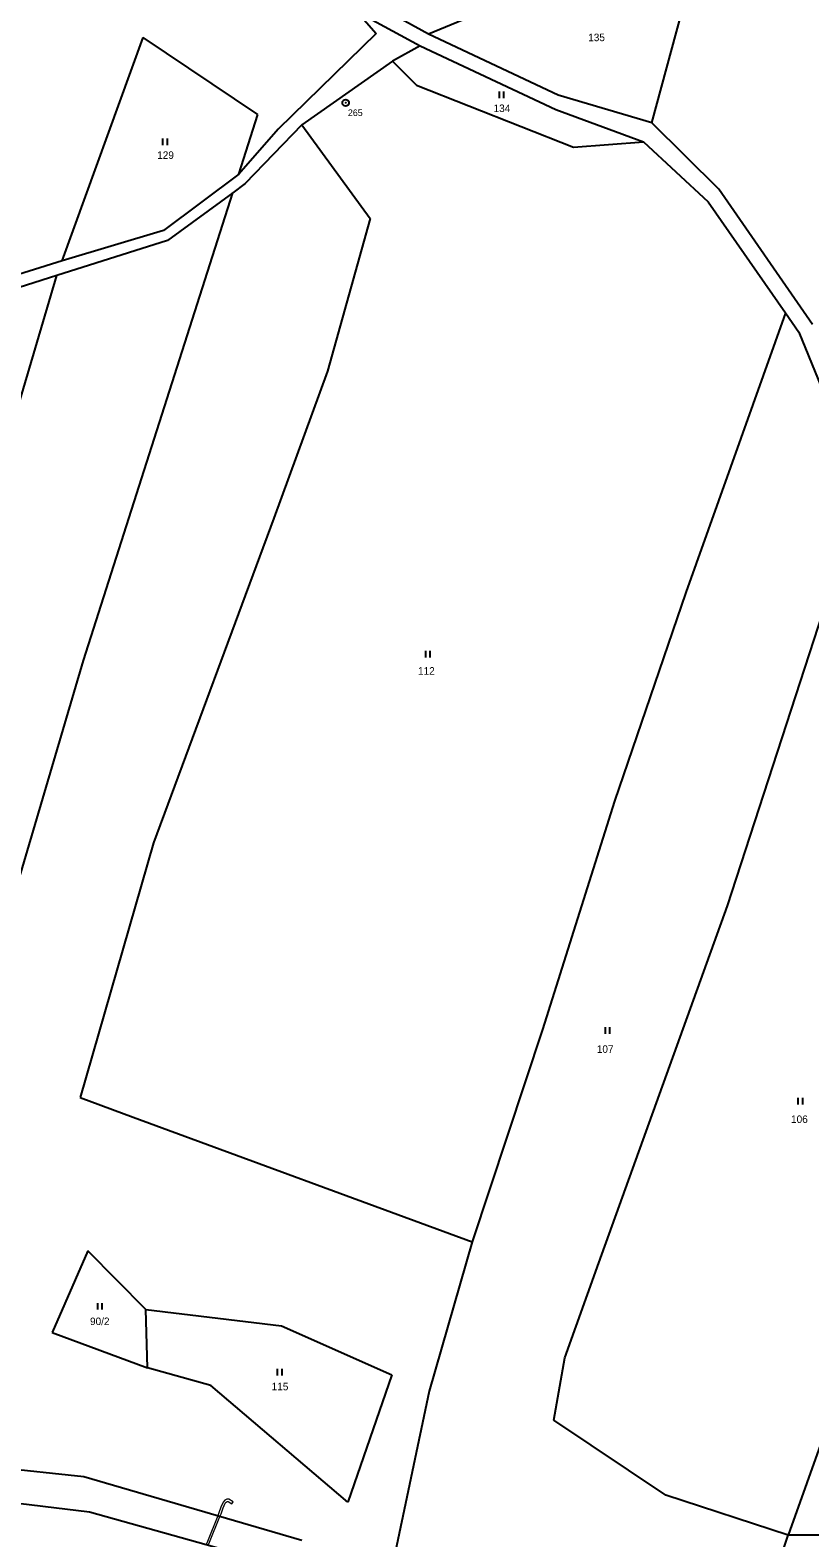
# Model space of a CAD drawing. Extents: x -791548 to -789311, y -1142631 to -1140855.
# Drawn here: x -790140.3 to -789963.7, y -1142168.7 to -1141827.2 of the extents above; entities that cross this region are included whole.
import ezdxf
from ezdxf.enums import TextEntityAlignment as Align

# ---------------------------------------------------------------- set-up
doc = ezdxf.new("R2010")
doc.units = 0
doc.header["$LTSCALE"] = 0.68
for name, color, linetype, lineweight in [('1', 7, 'Continuous', 25), ('13', 7, 'Continuous', 13), ('3', 7, 'Continuous', 25), ('8', 7, 'Continuous', 25)]:
    doc.layers.add(name, color=color, linetype=linetype, lineweight=lineweight)
doc.layers.add('2', color=7, linetype='Continuous')

msp = doc.modelspace()

# ---------------------------------------------------------------- linework, layer by layer
at = {"layer": '1'}
for p, q in [((-789999.52, -1141848.2), (-789985.77, -1141797.39)), ((-790001.61, -1141808.07), (-790050.12, -1141828.08)), ((-790050.12, -1141828.08), (-790064.67, -1141820.05)), ((-790066.32, -1141822.97), (-790051.96, -1141830.74)), ((-790066.32, -1141822.97), (-790061.95, -1141827.96)), ((-790133.08, -1141879.48), (-790114.77, -1141828.85)), ((-790088.74, -1141846.3), (-790114.77, -1141828.85)), ((-790061.95, -1141827.96), (-790084.19, -1141849.65)), ((-790020.74, -1141841.92), (-790050.12, -1141828.08)), ((-790051.96, -1141830.74), (-790058.23, -1141834.22)), ((-790051.96, -1141830.74), (-790021.22, -1141845.13)), ((-790058.23, -1141834.22), (-790078.78, -1141848.66)), ((-790058.23, -1141834.22), (-790052.8, -1141839.64)), ((-790052.8, -1141839.64), (-790017.22, -1141853.7)), ((-789999.52, -1141848.2), (-790020.74, -1141841.92)), ((-790093.06, -1141859.83), (-790088.74, -1141846.3)), ((-790021.22, -1141845.13), (-790001.42, -1141852.51)), ((-790084.19, -1141849.65), (-790093.06, -1141859.83)), ((-790078.78, -1141848.66), (-790091.66, -1141861.96)), ((-790078.78, -1141848.66), (-790063.31, -1141869.89)), ((-789984.32, -1141863.23), (-789999.52, -1141848.2)), ((-790017.22, -1141853.7), (-790001.42, -1141852.51)), ((-790001.42, -1141852.51), (-789986.75, -1141866.1)), ((-790093.06, -1141859.83), (-790110.11, -1141872.58)), ((-790091.66, -1141861.96), (-790094.45, -1141864.01)), ((-789963.14, -1141893.87), (-789984.32, -1141863.23)), ((-790128.27, -1141969.99), (-790094.45, -1141864.01)), ((-790094.45, -1141864.01), (-790109.23, -1141874.85)), ((-789986.75, -1141866.1), (-789969.22, -1141891.22)), ((-790063.31, -1141869.89), (-790073.01, -1141904.44)), ((-790110.11, -1141872.58), (-790133.08, -1141879.48)), ((-790109.23, -1141874.85), (-790134.26, -1141882.79)), ((-790133.08, -1141879.48), (-790188.11, -1141896.44)), ((-790134.26, -1141882.79), (-790188.03, -1141899.6)), ((-790157.72, -1141961.89), (-790134.26, -1141882.79)), ((-789969.22, -1141891.22), (-789991.81, -1141954.6)), ((-789969.22, -1141891.22), (-789966.17, -1141895.57)), ((-789966.17, -1141895.57), (-789950.79, -1141933.49)), ((-790073.01, -1141904.44), (-790085.16, -1141937.71)), ((-790085.16, -1141937.71), (-790112.38, -1142011.25)), ((-789991.81, -1141954.6), (-790007.99, -1142001.82)), ((-789982.4, -1142025.56), (-789958.67, -1141952.69)), ((-790155.05, -1142060.72), (-790128.27, -1141969.99)), ((-790007.99, -1142001.82), (-790024.29, -1142053.55)), ((-790112.38, -1142011.25), (-790128.98, -1142068.93)), ((-790011.51, -1142106.39), (-789982.4, -1142025.56)), ((-790024.29, -1142053.55), (-790040.24, -1142101.65)), ((-790128.98, -1142068.93), (-790117.03, -1142073.37)), ((-790117.03, -1142073.37), (-790040.24, -1142101.65)), ((-790040.24, -1142101.65), (-790049.96, -1142135.49)), ((-790127.24, -1142103.71), (-790135.35, -1142122.19)), ((-790114.13, -1142116.98), (-790127.24, -1142103.71)), ((-790019.25, -1142127.95), (-790011.51, -1142106.39)), ((-790114.13, -1142116.98), (-790083.39, -1142120.68)), ((-790113.76, -1142130.19), (-790114.13, -1142116.98)), ((-790135.35, -1142122.19), (-790113.76, -1142130.19)), ((-790083.39, -1142120.68), (-790058.43, -1142131.79)), ((-790099.43, -1142134.21), (-790113.76, -1142130.19)), ((-790021.7, -1142142), (-790019.25, -1142127.95)), ((-790058.43, -1142131.79), (-790068.36, -1142160.57)), ((-789955.95, -1142132.43), (-789968.63, -1142168.11)), ((-790068.36, -1142160.57), (-790099.43, -1142134.21)), ((-790049.96, -1142135.49), (-790058.25, -1142174.9)), ((-789996.33, -1142159), (-790021.7, -1142142)), ((-790128.15, -1142154.89), (-790154.8, -1142152.05)), ((-790078.79, -1142169.26), (-790128.15, -1142154.89)), ((-790167.62, -1142157.89), (-790126.91, -1142162.79)), ((-789968.63, -1142168.11), (-789996.33, -1142159)), ((-790126.91, -1142162.79), (-790092.94, -1142172.32)), ((-789973.41, -1142182.27), (-789968.63, -1142168.11)), ((-789934.5, -1142168), (-789968.63, -1142168.11))]:
    msp.add_line(p, q, dxfattribs=at)
at = {"layer": '13'}
for points in [[(-790097.11, -1142161.7), (-790097.56, -1142163.05), (-790097.83, -1142163.72), (-790097.36, -1142163.86), (-790097.1, -1142163.23), (-790096.65, -1142161.88), (-790096.2, -1142160.85), (-790095.96, -1142160.57), (-790095.69, -1142160.44), (-790095.51, -1142160.46), (-790094.64, -1142160.98), (-790094.38, -1142160.56), (-790095.35, -1142159.96), (-790095.79, -1142159.94), (-790096.26, -1142160.17), (-790096.62, -1142160.57)], [(-790097.36, -1142163.86), (-790097.83, -1142163.72), (-790100.2, -1142169.49), (-790100.5, -1142170.2), (-790100.01, -1142170.34), (-790099.74, -1142169.69)]]:
    msp.add_lwpolyline(points, close=True, dxfattribs=at)
at = {"layer": '3'}
for p, q in [((-790034.031, -1141842.6), (-790034.031, -1141841.1)), ((-790033.03, -1141842.6), (-790033.03, -1141841.1)), ((-790110.251, -1141853.26), (-790110.251, -1141851.76)), ((-790109.25, -1141853.26), (-790109.25, -1141851.76)), ((-790050.741, -1141969.27), (-790050.741, -1141967.77)), ((-790049.74, -1141969.27), (-790049.74, -1141967.77)), ((-790010.011, -1142054.53), (-790010.011, -1142053.03)), ((-790009.01, -1142054.53), (-790009.01, -1142053.03)), ((-789966.321, -1142070.5), (-789966.321, -1142069)), ((-789965.32, -1142070.5), (-789965.32, -1142069)), ((-790125.011, -1142117), (-790125.011, -1142115.5)), ((-790124.01, -1142117), (-790124.01, -1142115.5)), ((-790084.271, -1142131.93), (-790084.271, -1142130.43)), ((-790083.27, -1142131.93), (-790083.27, -1142130.43))]:
    msp.add_line(p, q, dxfattribs=at)
at = {"layer": '8'}
for radius in [0.75, 0.03]:
    msp.add_circle((-790068.86, -1141843.6398), radius, dxfattribs=at)

# ---------------------------------------------------------------- texts
at = {"layer": '2'}
for s, p in [('135', (-790012.029, -1141829.692)), ('134', (-790033.469, -1141845.735)), ('129', (-790109.669, -1141856.352)), ('112', (-790050.579, -1141973.172)), ('107', (-790010.079, -1142058.832)), ('106', (-789966.079, -1142074.712)), ('90/2', (-790124.569, -1142120.492)), ('115', (-790083.739, -1142135.262))]:
    msp.add_text(s, height=1.7, dxfattribs=at).set_placement(p, align=Align.CENTER)
at = {"layer": '8'}
msp.add_text('265', height=1.5, dxfattribs=at).set_placement((-790065.009, -1141846.647), align=Align.RIGHT)

doc.saveas('drawing.dxf')
